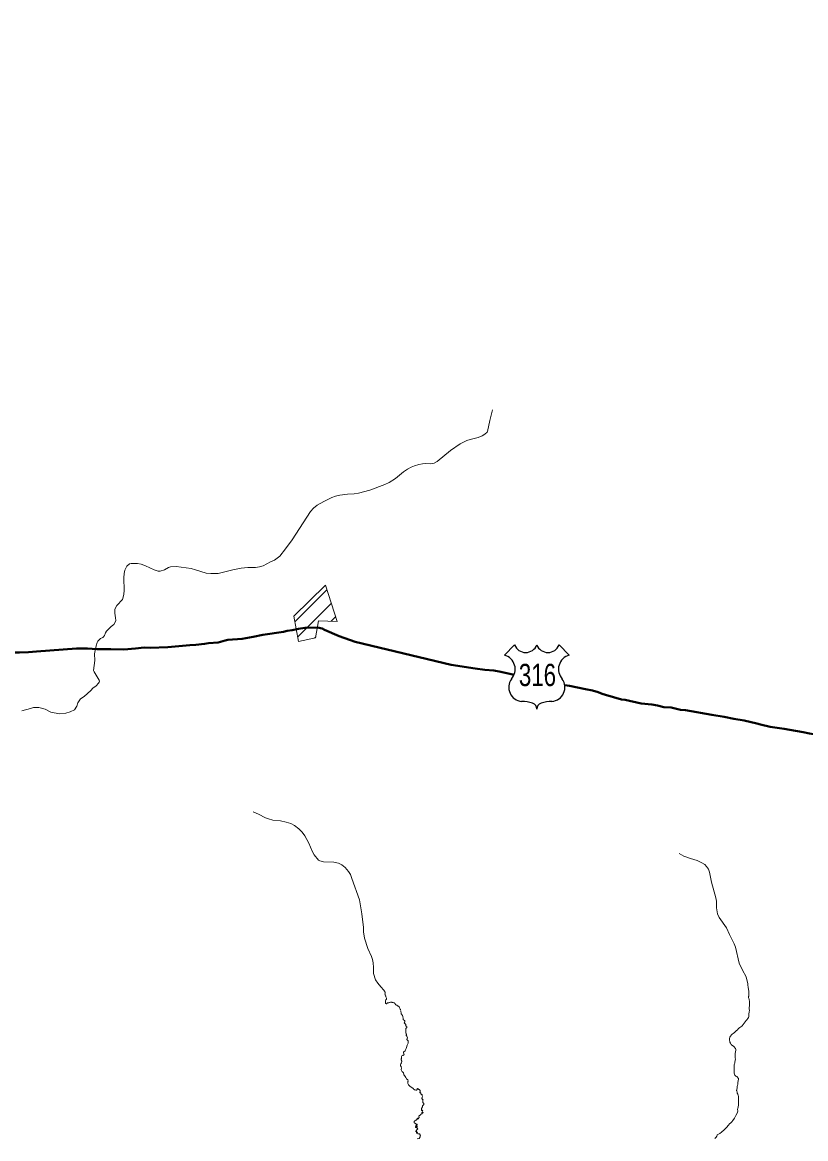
# Model space of a CAD drawing. Extents: x -1643653 to 4543381, y 1624270 to 13878484.
# Drawn here: x 611678 to 614145, y 8910758 to 8914272 of the extents above; entities that cross this region are included whole.
import ezdxf
from ezdxf.enums import TextEntityAlignment as Align

# ---------------------------------------------------------------- set-up
doc = ezdxf.new("R2010")
doc.units = 0
doc.header["$LTSCALE"] = 200
doc.layers.add('6', color=7, linetype='Continuous', lineweight=13)
doc.layers.add('60', color=7, linetype='Continuous', lineweight=13)

msp = doc.modelspace()

# ---------------------------------------------------------------- linework, layer by layer
at = {"layer": '6'}
for p, q in [((612536.6, 8912385.5), (612637.1, 8912486)), ((612545.6, 8912337.9), (612650.9, 8912443.2)), ((612651.1, 8912386.8), (612664.7, 8912400.5)), ((612598.1, 8912333.9), (612602.5, 8912338.2))]:
    msp.add_line(p, q, dxfattribs=at)
at = {"layer": '6', "lineweight": 25}
for p, q in [((613196.5, 8912280.5), (613228.5, 8912312.5)), ((613368.3, 8912312.5), (613400.3, 8912280.5))]:
    msp.add_line(p, q, dxfattribs=at)
at = {"layer": '6'}
for points in [[(613159.1, 8913052.5), (613150.7, 8913018.9), (613143.3, 8912984.7), (613141.8, 8912982.2), (613135, 8912975.7), (613126.6, 8912970.5), (613113.2, 8912965.1), (613088.7, 8912959.4), (613077.6, 8912955.9), (613056.8, 8912945.1), (613026.4, 8912924.2), (612984.3, 8912889.5), (612975.3, 8912885), (612962, 8912882.7), (612949.3, 8912883.3), (612938.2, 8912882.9), (612926.3, 8912880.4), (612913.6, 8912876.7), (612902.5, 8912872.2), (612890.6, 8912865.5), (612878, 8912856.9), (612853.6, 8912836.8), (612833.4, 8912823.5), (612819.3, 8912816.9), (612772.4, 8912799.4), (612736.7, 8912790.1), (612723.2, 8912787.6), (612701.8, 8912787.2), (612678, 8912783.9), (612664.5, 8912780.4), (612652.7, 8912776.3), (612628.1, 8912764), (612606.6, 8912751.9), (612595.2, 8912743), (612585.7, 8912732.6), (612528.2, 8912642.8), (612507.4, 8912614.5), (612488.7, 8912591.9), (612472.2, 8912579.6), (612459.6, 8912574.3), (612436.4, 8912561.7), (612424.6, 8912558.2), (612412.7, 8912555.7), (612388.1, 8912556.3), (612367.4, 8912554.2), (612341.2, 8912549.2), (612295.2, 8912537.7), (612271.4, 8912536.9), (612257.2, 8912538.1), (612223.7, 8912549.1), (612210.3, 8912552.6), (612162.7, 8912559.7), (612144.9, 8912558.7), (612138.8, 8912556.3), (612125.4, 8912548.8), (612112.3, 8912544.7), (612106, 8912544.6), (612092.8, 8912549.1), (612065.9, 8912561.3), (612052.4, 8912566.6), (612041.2, 8912568.8), (612020.6, 8912568.7), (612015.4, 8912567.7), (612007.7, 8912559.9), (612001.2, 8912548)], [(612001.2, 8912548), (611998.8, 8912537.7), (611997.8, 8912523.3), (611998.9, 8912484.2), (611997.9, 8912472.3), (611995, 8912458.1), (611993.6, 8912455.4), (611976.2, 8912436.9), (611969.4, 8912425.1), (611969, 8912412.8), (611971.8, 8912397.5), (611972.1, 8912388.9), (611971.3, 8912385.8), (611966.1, 8912376.9), (611957.4, 8912370.8), (611942.7, 8912356), (611939.6, 8912350.1), (611936.9, 8912341.8), (611934.1, 8912337.6), (611931.6, 8912335.8), (611923.8, 8912332.9), (611915.6, 8912324.2), (611913.7, 8912320.5), (611910.8, 8912309.8), (611905.7, 8912284.3), (611906.7, 8912263.3), (611902.5, 8912231.9), (611903.9, 8912227.7), (611920, 8912201.1), (611920.7, 8912198.1), (611920.3, 8912194.8), (611918.3, 8912191.9), (611910.3, 8912183.8), (611900.1, 8912176.6), (611894.1, 8912169.3), (611873.3, 8912150.5), (611860.8, 8912142.2)], [(611860.8, 8912142.2), (611860.8, 8912142.2), (611852.4, 8912130.6), (611850.2, 8912119.3), (611842.5, 8912108), (611828.6, 8912102), (611814.7, 8912097.6), (611794.8, 8912095), (611768, 8912101.1), (611749.8, 8912110.6), (611730.3, 8912115), (611713.8, 8912115.8), (611696.5, 8912110.6), (611687.8, 8912108), (611677, 8912104.6)], [(612405.4, 8911786.9), (612421.9, 8911779.7), (612444.2, 8911767.9), (612452.9, 8911764.7), (612467, 8911761.3), (612491.4, 8911758.4), (612508.9, 8911754.9), (612524, 8911749.8), (612535, 8911743.9), (612548.6, 8911733.8), (612559.7, 8911722.7), (612568.1, 8911711.9), (612580.6, 8911688.2), (612590.9, 8911663.6), (612597.2, 8911651.2), (612610.8, 8911634.7), (612615.1, 8911632.4), (612626.2, 8911629.9), (612658.6, 8911628.8), (612673.5, 8911625.1), (612683.9, 8911620.1), (612694.8, 8911611.3), (612705, 8911599.6), (612711.5, 8911589.3), (612716.3, 8911577.6), (612739.5, 8911510.5), (612747.7, 8911466.3), (612752.2, 8911422.9), (612752.6, 8911408.8), (612755.4, 8911389), (612765.9, 8911357.3), (612777.4, 8911331.4), (612780.4, 8911322.6), (612782.9, 8911311.6), (612784.4, 8911297.5), (612784.2, 8911278.4), (612790.5, 8911258.6), (612797.4, 8911247.3), (612807.2, 8911235.8), (612817.1, 8911225.9)], [(613746.6, 8911655.6), (613761.8, 8911647), (613782.4, 8911639.6), (613803.8, 8911633.7), (613818.3, 8911626.8), (613827.9, 8911620.8), (613832.9, 8911615.2), (613838.7, 8911606.9), (613842.3, 8911596.7), (613848.4, 8911566.1), (613862.4, 8911516.5), (613864.1, 8911505.6), (613864.4, 8911484.4), (613867.7, 8911465.5), (613872.8, 8911454.6), (613895.5, 8911422.3), (613905.6, 8911400.5), (613920.2, 8911371.9), (613924.2, 8911361), (613935.1, 8911310.7), (613946.5, 8911288.1), (613957.4, 8911267.5), (613963, 8911245.3)], [(612817.1, 8911225.9), (612817.4, 8911225), (612818, 8911223.9), (612818.6, 8911222.4), (612819.6, 8911220.8), (612820.4, 8911219.5), (612820.6, 8911218.7), (612820.6, 8911217.4), (612820.3, 8911215.9), (612820.2, 8911213.9), (612820.4, 8911213), (612821.1, 8911211.6), (612821.3, 8911210.5), (612821, 8911209.4)], [(613966, 8911218.5), (613966.2, 8911213.3), (613966.1, 8911210.4), (613965.8, 8911207), (613965.3, 8911205.2), (613964.9, 8911202.2), (613965.7, 8911199.6), (613966.6, 8911197.7), (613967.8, 8911188.8), (613968.6, 8911182.6), (613968.1, 8911177), (613967.4, 8911169.7), (613967.3, 8911166.2), (613967.7, 8911163.2), (613967.1, 8911156.4), (613966.2, 8911150.8), (613965.8, 8911148.1), (613965.7, 8911142.8), (613964.8, 8911139.7), (613963.2, 8911136.5), (613959.5, 8911132.2), (613957.2, 8911129.9), (613954.8, 8911125.9), (613951.1, 8911121.5), (613948.5, 8911117.8), (613945.3, 8911113.3), (613943.9, 8911111.8), (613937.8, 8911108.3), (613933.6, 8911104.8), (613930.1, 8911100.6), (613926.5, 8911097.3), (613920.7, 8911092.4), (613917, 8911089.5), (613913.8, 8911087), (613911, 8911084.6), (613908.2, 8911080.6), (613906.3, 8911077.3), (613905.5, 8911074), (613905.7, 8911070.7)], [(613963, 8911245.3), (613963.4, 8911239.5), (613963.5, 8911237), (613964, 8911233.7), (613964.6, 8911229.1), (613965.9, 8911221.6), (613966.2, 8911220), (613966.3, 8911218.8), (613966.4, 8911218.5)], [(612821, 8911209.4), (612821.6, 8911208.3), (612822.4, 8911206.7), (612823.2, 8911204.4), (612824.9, 8911200.9), (612825.3, 8911199.8), (612825.2, 8911198.6), (612824.6, 8911197.1), (612823.1, 8911195.1), (612822, 8911193.1), (612821.4, 8911190.8), (612822.3, 8911187), (612822.3, 8911184.5), (612822.3, 8911183.5)], [(612822.3, 8911183.6), (612823.9, 8911183.1), (612824.8, 8911183), (612825.5, 8911183.1), (612826.4, 8911183.6), (612827.5, 8911185), (612828.1, 8911185.7), (612829, 8911186), (612830.5, 8911186), (612832.3, 8911185.9), (612834.3, 8911186.6), (612835.2, 8911187), (612837.1, 8911188), (612838.2, 8911188.2), (612839.3, 8911188), (612841.9, 8911187.6), (612843.1, 8911187.2), (612844.3, 8911186.8), (612845.2, 8911186.6)], [(612845.8, 8911186.4), (612847.8, 8911186.2), (612848.8, 8911185.9), (612850.1, 8911185.3), (612851.1, 8911183.4), (612851.8, 8911182.1), (612853.2, 8911180.4), (612854.8, 8911179.4), (612856.6, 8911178.8), (612858, 8911178), (612859.3, 8911176.8), (612860.2, 8911175.8), (612861.6, 8911175.2), (612863.6, 8911174.4), (612864.9, 8911173.1), (612865.7, 8911171.2), (612866, 8911169.8), (612866.6, 8911168.1), (612868, 8911166.1), (612868.8, 8911164.7), (612869.4, 8911162.7), (612869.5, 8911162.2)], [(612870, 8911160.6), (612870.2, 8911158.5), (612871, 8911154.3), (612871.2, 8911152.6), (612871.6, 8911151.3), (612872.5, 8911149.8), (612875.7, 8911145.6), (612876.6, 8911143.7), (612876.9, 8911140.7), (612877, 8911138.6), (612877, 8911136), (612877.1, 8911134.4), (612877.8, 8911133.5), (612878.8, 8911132.1), (612881.5, 8911129.7), (612882.5, 8911128.8), (612882.8, 8911126.8), (612882.6, 8911126.4), (612881.7, 8911124.8), (612881, 8911123.3), (612881, 8911122.3), (612881.3, 8911121.4), (612882.3, 8911120.3), (612883.6, 8911119.2), (612885, 8911118.3), (612885.8, 8911117.8), (612886.2, 8911116.9), (612886.3, 8911116), (612885.4, 8911114.6), (612885.2, 8911114.1), (612885.6, 8911113.2), (612886.1, 8911112.8), (612886.9, 8911112.2), (612887.6, 8911111.8), (612888.3, 8911111.2), (612888.6, 8911110.8), (612888.7, 8911110.1), (612888.7, 8911109.2), (612888.5, 8911108.4), (612887.9, 8911106.8), (612887.2, 8911106.1), (612886.2, 8911105), (612885.7, 8911103.9), (612885.5, 8911103.1), (612885.7, 8911101.4), (612886, 8911100.1), (612886, 8911096.1)], [(612886, 8911096.1), (612886, 8911095.7), (612885.7, 8911092.9), (612885.7, 8911091.7), (612885.9, 8911090.9), (612886.2, 8911089.9), (612886.9, 8911088.7), (612887.5, 8911087), (612887.5, 8911085.5), (612887.3, 8911084.3), (612887.3, 8911083.3), (612887.7, 8911082.1), (612888.8, 8911080.4), (612889.9, 8911078.4), (612890.8, 8911075.4), (612890.9, 8911074.4), (612890.3, 8911072.9), (612889.5, 8911072.2), (612889.2, 8911071.4), (612889.4, 8911070.4), (612890, 8911069.6), (612891.6, 8911068.2), (612893, 8911066.1), (612893.2, 8911064.9), (612893.2, 8911062.9), (612893.2, 8911061.3), (612893.3, 8911060.2), (612893.2, 8911058.7), (612892.1, 8911056.8), (612890.5, 8911052.5), (612888.3, 8911044.8), (612887.3, 8911042), (612885.3, 8911038), (612883.9, 8911035.1), (612882.5, 8911033.2), (612880.3, 8911032.3), (612879.2, 8911031.5), (612878.8, 8911030.7), (612878.8, 8911029.7), (612878.8, 8911028.4), (612879.6, 8911025.6), (612880.2, 8911023.6), (612880.1, 8911022.8), (612879.7, 8911022.1), (612879.1, 8911021.3), (612877.8, 8911020.6), (612876.9, 8911020.3), (612875.7, 8911019.9), (612873.7, 8911018.5), (612872.5, 8911016.7), (612872.3, 8911013), (612871.7, 8911010.8), (612871.5, 8911009.2), (612871.5, 8911007.4), (612871.6, 8911006.2), (612872, 8911005.1), (612872.5, 8911003.1), (612873, 8911001.7), (612872.9, 8911000.1), (612872.7, 8910998.3), (612872.1, 8910997.4), (612871.8, 8910996.5), (612870.5, 8910994.1), (612869.2, 8910990.6), (612868.7, 8910989.1), (612868.6, 8910988.1), (612869.5, 8910986.6), (612870, 8910986.1), (612870.8, 8910984.9), (612871.2, 8910984.1), (612871.4, 8910982.9), (612871.7, 8910981.6), (612872.1, 8910980.7), (612872.2, 8910979.9), (612871.8, 8910978.7), (612871.1, 8910977.3), (612871.1, 8910976.3), (612871.5, 8910974.7), (612872.4, 8910973.2), (612873.5, 8910970.8), (612874.1, 8910968.9), (612874.6, 8910968.5), (612875.2, 8910968.6), (612875.7, 8910968.5), (612876.9, 8910968), (612877.6, 8910966.4), (612878, 8910965.1), (612878.2, 8910963.9), (612879.1, 8910961.1), (612880, 8910959.1), (612881.5, 8910957.1), (612884, 8910953.5), (612886, 8910950.8), (612887.1, 8910948.4), (612888.1, 8910946.9), (612889.3, 8910945.7), (612891.2, 8910944.1), (612892.2, 8910942.9), (612892.5, 8910941.8), (612892.8, 8910940.3), (612892.8, 8910939.2)], [(613905.7, 8911070.7), (613906.7, 8911061.6), (613907.9, 8911058.6), (613910.9, 8911054.8), (613912.8, 8911052.8), (613917.7, 8911049.7), (613921.4, 8911046.2), (613922.5, 8911044.6), (613923.9, 8911041.5), (613924.7, 8911039.5), (613924.8, 8911036.7), (613923.9, 8911031.6), (613923.4, 8911026.2), (613923, 8911016), (613923.2, 8911011.7), (613923.7, 8911009.6)], [(613923.7, 8911009.6), (613923.4, 8911004.1), (613922.3, 8910999.1), (613921.6, 8910995.9), (613920.6, 8910993.5), (613920.2, 8910990.8), (613919.6, 8910983.3), (613919.7, 8910972.5), (613919.7, 8910965.9), (613920, 8910963.9), (613922, 8910958.4), (613923, 8910957), (613925.6, 8910955.1), (613927.6, 8910954), (613928.3, 8910953.5)], [(612892.8, 8910939.2), (612892.5, 8910938), (612892, 8910936.1), (612891.9, 8910933.6), (612892.3, 8910931.7), (612893.3, 8910929.9), (612894.7, 8910927.6), (612896.3, 8910925.2), (612898.7, 8910923), (612900.5, 8910921.5), (612901.9, 8910920.9), (612903.3, 8910920.3), (612905.2, 8910919.5), (612906.3, 8910918.5), (612908, 8910917.3), (612909.5, 8910915.3), (612910.4, 8910913.9), (612912.2, 8910913.1), (612913.4, 8910912.4), (612915.2, 8910911.6), (612917, 8910911.1), (612918, 8910910.9), (612919.8, 8910910.9), (612920.8, 8910911.3), (612921, 8910911.8), (612921.2, 8910912.6), (612921.2, 8910913.6), (612921.1, 8910914.2), (612921.6, 8910915), (612922.3, 8910915.8), (612922.8, 8910915.8), (612924, 8910915.4), (612925, 8910914.6), (612926.6, 8910913.2), (612928, 8910912.6), (612929.2, 8910911.8), (612930.2, 8910911.3), (612930.6, 8910911), (612931, 8910910.2), (612931.2, 8910908.8), (612931.2, 8910907.2), (612930.8, 8910905.6), (612930, 8910904.3), (612929.8, 8910903.6), (612929.7, 8910903), (612929.7, 8910902.6), (612930.1, 8910902.2), (612930.5, 8910902.2), (612931.1, 8910902.5), (612931.5, 8910902.7), (612932.4, 8910902.8), (612932.9, 8910902.7), (612933.5, 8910902.1), (612933.5, 8910900.6), (612933.5, 8910899.2), (612933.7, 8910898.3), (612934.1, 8910897.7), (612934.8, 8910897.4), (612935.7, 8910897.2), (612936.4, 8910896.8), (612937.1, 8910896.1), (612937.5, 8910895), (612937.7, 8910893.2), (612937.9, 8910890.7), (612937.7, 8910888.7), (612937.3, 8910887.1), (612936.7, 8910885.7), (612936.4, 8910884.7), (612937, 8910883.8), (612937.3, 8910883.4), (612937.4, 8910882.7), (612937.4, 8910882.1), (612937.5, 8910881.7), (612938, 8910881.3), (612938.7, 8910881.5), (612939.3, 8910881.6), (612940, 8910881.1), (612939.7, 8910880.3), (612939.3, 8910879.9), (612939, 8910878.4), (612938.9, 8910876.9), (612939.1, 8910875.8), (612939.3, 8910875), (612939.5, 8910873.6), (612939.9, 8910872.2), (612940.3, 8910871.4), (612941.8, 8910870.4), (612942.5, 8910869.8), (612942.9, 8910869.2), (612943, 8910868.4), (612942.9, 8910867), (612942.5, 8910865.5), (612941.6, 8910864.4), (612940.6, 8910863.4), (612938.5, 8910861.4), (612938.1, 8910860.8), (612937.9, 8910859.8), (612937.9, 8910858.4), (612937.8, 8910857.7), (612937.7, 8910856.6), (612937.5, 8910855.9)], [(613928.3, 8910953.5), (613933.1, 8910947.2), (613933.2, 8910944.8), (613932.9, 8910941.7), (613931.1, 8910934), (613930.9, 8910929.6), (613929.9, 8910925.9), (613929.5, 8910923.4), (613929.8, 8910920.8), (613929.5, 8910918.5), (613927.9, 8910913.2), (613927.6, 8910910.2), (613927.8, 8910908.3), (613928.8, 8910904.8), (613929.5, 8910901.6), (613931.4, 8910897.8), (613932.2, 8910895.3), (613933, 8910891.4), (613933.2, 8910886.4), (613933.6, 8910872.7), (613934, 8910868.4), (613933.5, 8910863.2), (613930.9, 8910853.3), (613930.7, 8910851.1), (613931.3, 8910845.2), (613930.7, 8910841.7), (613929, 8910838), (613924.9, 8910830.6), (613920.9, 8910822.8), (613916, 8910815.5), (613913, 8910811.6), (613909, 8910808), (613905.3, 8910805), (613901.6, 8910800.4), (613896.1, 8910793.5), (613888.2, 8910785.5), (613880.1, 8910779), (613874.6, 8910774.1), (613870.3, 8910772.2), (613866.8, 8910770)], [(612937.5, 8910855.9), (612936.5, 8910855.3), (612935.9, 8910854.3), (612935.5, 8910853.3), (612935.6, 8910851.6), (612935.5, 8910849.7), (612935.3, 8910847.8), (612935.5, 8910847), (612935.9, 8910846.6), (612936.3, 8910846.8), (612936.8, 8910847.3), (612937.2, 8910847.6), (612937.9, 8910847.9), (612938.5, 8910847.8), (612938.8, 8910847.2), (612939, 8910846.5), (612938.4, 8910844.6), (612937.7, 8910843), (612937.5, 8910842.2), (612937.5, 8910841.6), (612937.9, 8910841.1), (612938.3, 8910841.1), (612938.8, 8910841.1), (612940.1, 8910840.8), (612940.3, 8910840.4), (612940.3, 8910839.8), (612939.7, 8910839.6), (612938.9, 8910839.6), (612938.1, 8910839.8), (612937.2, 8910840.1), (612936.6, 8910840.2), (612936.3, 8910839.8), (612936.4, 8910839), (612936.9, 8910838.1), (612937.3, 8910836.9), (612936.7, 8910836), (612935.8, 8910836), (612934.5, 8910835.4), (612933.3, 8910835), (612932.8, 8910834.5), (612932.2, 8910833.6), (612931.2, 8910831.8), (612928.7, 8910831.4), (612927.6, 8910830.3), (612927.2, 8910828.9), (612927.1, 8910827.7), (612927.6, 8910825.7), (612927.8, 8910825.1), (612927.6, 8910824.5), (612927.1, 8910824), (612926.3, 8910823.6), (612926.1, 8910822.9), (612926.2, 8910822.3), (612926.4, 8910821.5), (612926.1, 8910821.2), (612925.9, 8910821.2), (612925.6, 8910821.5), (612925.1, 8910822), (612924.7, 8910822.3), (612924.5, 8910822.6), (612924.1, 8910822.8), (612923.6, 8910822.8), (612923.1, 8910822.6), (612923, 8910822.1), (612923.2, 8910821.4), (612923.5, 8910820.8), (612923.9, 8910820.1), (612924.1, 8910819.7), (612924, 8910819.3), (612923.6, 8910819), (612923.2, 8910819.1), (612922.8, 8910819.5), (612922, 8910820.1), (612921.6, 8910820.4), (612921.1, 8910820.4), (612920.5, 8910820.1), (612920, 8910819.4), (612919, 8910817.4), (612917.9, 8910816.3), (612917, 8910815.9), (612914.6, 8910814.4), (612913.7, 8910814.1), (612912.9, 8910813.4), (612912.3, 8910811.9), (612912.4, 8910809.3), (612912.5, 8910808.5), (612913.1, 8910807.8), (612913.4, 8910807.3), (612913.9, 8910806.9), (612914.8, 8910806.6), (612915.5, 8910806.3), (612916.3, 8910806.1), (612916.7, 8910805.6), (612917.3, 8910804.8), (612917.7, 8910804.2), (612918.1, 8910803.9), (612918.5, 8910803.7), (612919, 8910803.6), (612919.5, 8910803.7), (612920.1, 8910803.9), (612920.5, 8910804)], [(612920.5, 8910804), (612921, 8910804), (612921.5, 8910803.5), (612921.8, 8910802.7), (612921.5, 8910801.5), (612921.2, 8910801.1), (612920.3, 8910800.4), (612919.7, 8910800.2), (612918.6, 8910800.1), (612918, 8910800), (612917.5, 8910799.4), (612917.1, 8910799.1), (612916.9, 8910798.1), (612917, 8910796.9), (612916.8, 8910796.3), (612916.5, 8910795.6), (612916.4, 8910794.9), (612916.2, 8910794), (612916.5, 8910793.5), (612917, 8910793), (612917.8, 8910793.2), (612918.5, 8910794), (612919.3, 8910795.5), (612919.6, 8910796.3), (612919.9, 8910797.1), (612920.4, 8910797.3), (612920.9, 8910797.2), (612921.2, 8910796.6), (612921.4, 8910795.9), (612921, 8910794.6), (612920.5, 8910793.2), (612920.6, 8910792.4), (612921, 8910791.5), (612921.7, 8910791.2), (612922.7, 8910790.6), (612923.1, 8910790), (612923.3, 8910789.2), (612923.1, 8910788.2), (612922.4, 8910787.4), (612921.2, 8910787), (612920.4, 8910786.4), (612919.8, 8910785.5), (612919.6, 8910784.1), (612919.1, 8910783.5), (612917.4, 8910782), (612917, 8910781.2), (612916.8, 8910780.7), (612917.3, 8910780.3), (612918, 8910780.7), (612918.8, 8910781.4), (612919.4, 8910781.8), (612920, 8910781.8), (612920.3, 8910781.5), (612920.4, 8910780.8), (612919.7, 8910779.1), (612919.2, 8910777.3), (612919.2, 8910776.4), (612919.5, 8910775.9), (612920, 8910775.8), (612920.5, 8910775.9), (612921, 8910776), (612921.5, 8910777.2), (612921.8, 8910777.6), (612922.3, 8910777.6), (612922.8, 8910777.2), (612923.1, 8910776.6), (612923.5, 8910774.8), (612923.8, 8910774.1), (612924.1, 8910773.6), (612924.8, 8910773), (612925.6, 8910772.9), (612926.5, 8910773.2), (612927.1, 8910773.6), (612928.2, 8910773.9), (612929, 8910773.8), (612929.5, 8910773.4), (612929.9, 8910772.8), (612930.3, 8910771.7), (612930.8, 8910770.1), (612931.6, 8910768.3), (612931.5, 8910767), (612931.1, 8910764.1)], [(612931.1, 8910764.1), (612928.1, 8910759.2), (612921.5, 8910757.2)], [(613866.8, 8910769.9), (613866, 8910767.8), (613864.8, 8910765.7), (613863.2, 8910763.3), (613858.9, 8910758.2)]]:
    msp.add_lwpolyline(points, dxfattribs=at)
msp.add_lwpolyline([(612533.2, 8912403.4), (612632.5, 8912500.1), (612669.3, 8912386.3), (612611.2, 8912388.1), (612601.8, 8912334.6), (612548.3, 8912323.5)], close=True, dxfattribs=at)
at = {"layer": '6', "lineweight": 40}
for points in [[(611849.1, 8912301.5), (611883.1, 8912301.1), (611912.9, 8912298.6), (611956.6, 8912299.4), (611998, 8912298.2), (612034.4, 8912300.8), (612062.1, 8912304), (612080.2, 8912303.3), (612136.2, 8912305), (612205.9, 8912312.1), (612224, 8912312.5), (612252.3, 8912315.6), (612263.9, 8912317.7), (612294.8, 8912320.4), (612302.5, 8912322), (612316.8, 8912326.8), (612325.2, 8912328.8), (612370.8, 8912332), (612405.4, 8912337.7), (612435.2, 8912344), (612500.6, 8912353.4), (612512.3, 8912356.6), (612528.3, 8912358.5), (612547.5, 8912363.6), (612568.3, 8912366), (612607.2, 8912366.8), (612622, 8912364.3), (612629.4, 8912360.3), (612675.8, 8912339.5), (612726, 8912322.1), (613028.9, 8912249.9)], [(611495.6, 8912282.8), (611522.6, 8912283.1), (611612.8, 8912289.8), (611627.7, 8912289.9), (611652.6, 8912288.3), (611668.8, 8912288.2), (611697.4, 8912289.8), (611723, 8912291.6), (611849.1, 8912301.5)], [(613028.9, 8912249.9), (613104.3, 8912237.7), (613134.5, 8912234.3), (613163.2, 8912232.2), (613185.3, 8912228.2), (613226.8, 8912218.5)], [(613386.4, 8912186.2), (613401.2, 8912183.6), (613452.1, 8912172.7), (613474.2, 8912168.8), (613491.2, 8912163.9), (613503.7, 8912158.5), (613514.7, 8912154.8), (613564.8, 8912141), (613576.6, 8912139.3), (613626.7, 8912128.5), (613660.6, 8912124.5), (613678.3, 8912121.5), (613698.2, 8912117), (613721.1, 8912115.6), (613750.5, 8912108.4), (613766.3, 8912107.4), (613849.7, 8912091.9), (613888.1, 8912085.9), (613919, 8912079.5), (613951.5, 8912074.8), (613991.2, 8912065.2), (614002.3, 8912061.8), (614033.2, 8912054.9), (614077.8, 8912048.2), (614095.5, 8912045.1)], [(614095.5, 8912045.1), (614137.1, 8912037.7), (614156.6, 8912033.3), (614189.2, 8912028.5), (614215.5, 8912021.7), (614263.5, 8912005.4), (614314.9, 8911983.3), (614359.3, 8911958.1), (614413.5, 8911919.6), (614418.7, 8911918.6), (614421.7, 8911917.2), (614435.2, 8911906.1)]]:
    msp.add_lwpolyline(points, dxfattribs=at)
at = {"layer": '6', "lineweight": 25}
for centre, radius, start, end in [((613263.4, 8912325.9), 37.4, 200.9593, 339.0407), ((613333.4, 8912325.9), 37.4, 200.9593, 339.0407), ((613184.1, 8912236.1), 46.1, 317.5721, 74.3689), ((613412.7, 8912236.1), 46.1, 105.6277, 222.4279), ((613254.8, 8912179.1), 44.9, 144.7373, 264.6578), ((613342, 8912179.1), 44.9, 275.3422, 35.2627), ((613250.4, 8912016.4), 118, 72.8937, 89.9006), ((613346.4, 8912016.4), 118, 90.0994, 107.1063), ((613279.5, 8912111.1), 18.9, 357.6934, 72.9296), ((613317.3, 8912111.1), 18.9, 107.0704, 182.3065)]:
    msp.add_arc(centre, radius, start, end, dxfattribs=at)
at = {"layer": '60', "lineweight": 25}
msp.add_spline([(814781, 9009175.5), (814787.2, 9009173.4), (814796.9, 9009173.4), (814799.4, 9009172.4), (814805.1, 9009174.5), (814805.6, 9009176.5), (814811.7, 9009179.5), (814811.7, 9009179.5), (814801.5, 9009181), (814790.7, 9009181.5), (814784.1, 9009183.1), (814777.4, 9009185.1), (814778.4, 9009175.5)], degree=3, dxfattribs=at)

# ---------------------------------------------------------------- texts
at = {"layer": '6', "width": 0.75}
msp.add_text('316', height=70, dxfattribs=at).set_placement((613300.4, 8912182.9), align=Align.CENTER)

doc.saveas('drawing.dxf')
